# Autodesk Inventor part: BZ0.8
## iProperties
Created: 2002-07
Part Number: BZ0.8
Document SubType Name: Modeling
Designer: A. Maffi
Description: BENZING d.0,8 DIN 6799
Control State: 0
Master: False
Checked Out: False
Shininess: 70.0
Length Units: 11269
Angle Units: 11279
Time Units: 11290
Mass Units: 11284
Length Display Precision: 3
Angle Display Precision: 2
Density: 0.0
Volumn: 0.0
Area: 0.0
PropertySet Name: Model Information
Author: rmjbm2
Revision Number: /
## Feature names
1. Extrusion4
